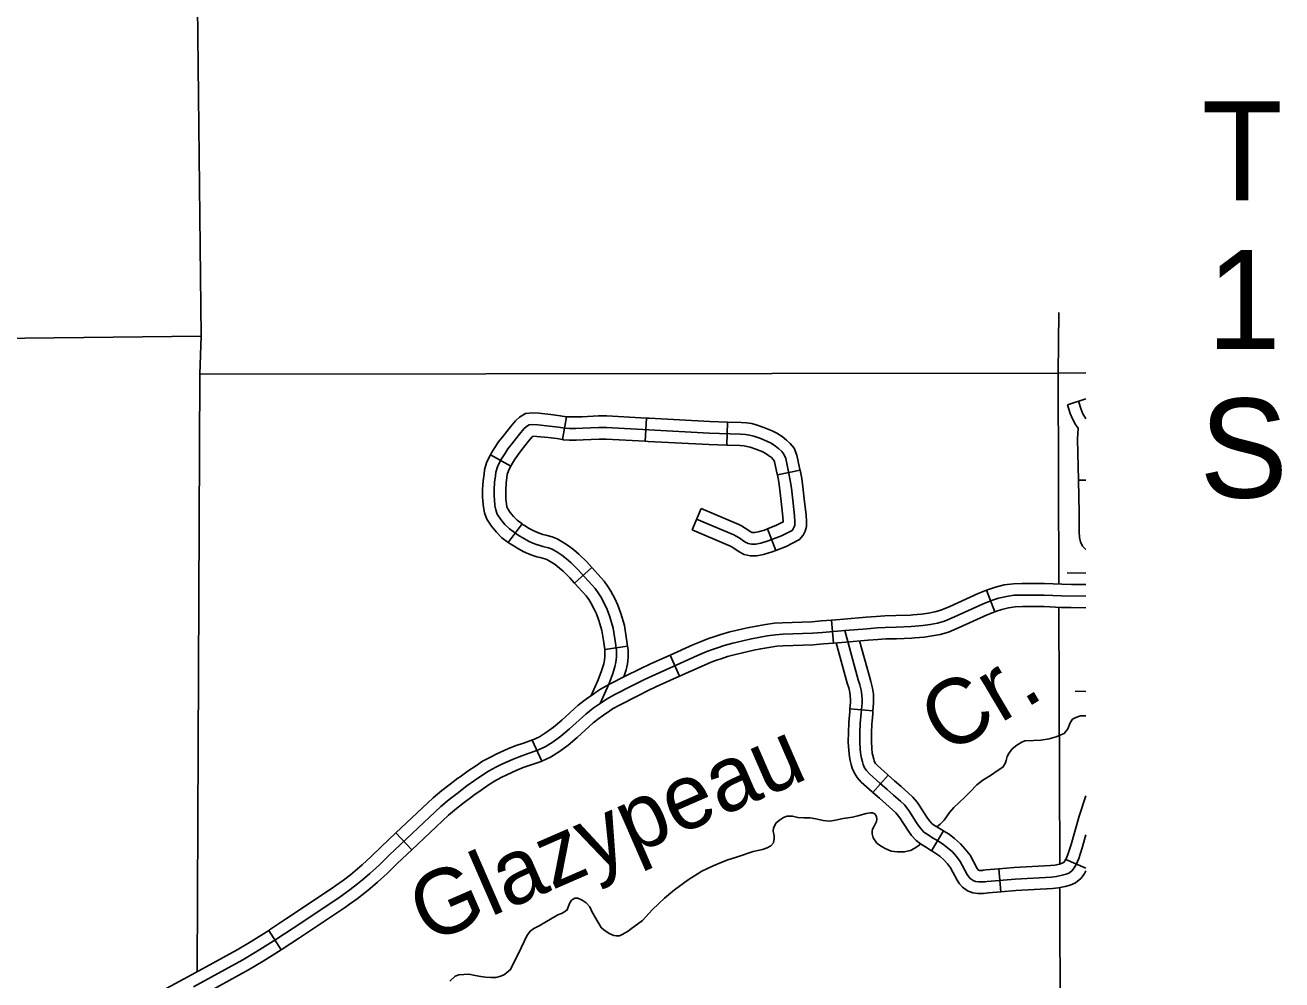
# Model space of a CAD drawing. Extents: x -3711 to 825, y -151 to 1050.
# Drawn here: x -2612.2 to -2520.9, y 335.8 to 405.1 of the extents above; entities that cross this region are included whole.
import ezdxf

# ---------------------------------------------------------------- set-up
doc = ezdxf.new("R2010")
doc.units = 0
for name, color, linetype in [('Default', 7, 'Continuous'), ('Level 31', 7, 'Continuous'), ('Level 32', 7, 'Continuous'), ('Level 35', 7, 'Continuous'), ('Level 4', 7, 'Continuous'), ('Level 5', 7, 'Continuous')]:
    doc.layers.add(name, color=color, linetype=linetype)

msp = doc.modelspace()

# ---------------------------------------------------------------- linework, layer by layer
at = {"layer": 'Level 31'}
for p, q in [((-2541.757, 362.511), (-2542.373, 364.075)), ((-2553.612, 361.903), (-2553.471, 360.228)), ((-2564.648, 357.829), (-2565.343, 359.359)), ((-2574.658, 351.659), (-2575.35, 353.191)), ((-2574.658, 351.659), (-2574.658, 351.659)), ((-2585.247, 346.438), (-2584.093, 345.215)), ((-2593.591, 337.939), (-2594.49, 339.36))]:
    msp.add_line(p, q, dxfattribs=at)
for points in [[(-2535.146, 365.319), (-2536.513, 365.34)], [(-2542.373, 364.075), (-2542.295, 364.106), (-2541.716, 364.299), (-2541.077, 364.453), (-2540.412, 364.544), (-2539.769, 364.564), (-2538.999, 364.564), (-2538.145, 364.564), (-2536.896, 364.505), (-2536.19, 364.494)], [(-2536.19, 364.494), (-2535.146, 364.478)], [(-2535.146, 363.638), (-2536.923, 363.665), (-2538.165, 363.723), (-2538.999, 363.723), (-2539.756, 363.723), (-2540.342, 363.706), (-2540.921, 363.626), (-2541.483, 363.49), (-2542.007, 363.315), (-2542.648, 363.063), (-2544.686, 362.131), (-2545.406, 361.83), (-2545.923, 361.679), (-2546.451, 361.582), (-2546.995, 361.509), (-2547.83, 361.431), (-2548.917, 361.393), (-2549.712, 361.373), (-2550.314, 361.334), (-2551.032, 361.276), (-2552.654, 361.14), (-2554.273, 361.004), (-2554.991, 360.946), (-2557.16, 360.87), (-2557.677, 360.838), (-2558.291, 360.752), (-2558.916, 360.644), (-2559.436, 360.538), (-2560.791, 360.223), (-2561.415, 360.052), (-2561.901, 359.897)], [(-2542.373, 364.075), (-2542.977, 363.837), (-2545.023, 362.901), (-2545.687, 362.623), (-2546.117, 362.498), (-2546.582, 362.412), (-2547.09, 362.344), (-2547.715, 362.286)], [(-2541.756, 362.511), (-2542.319, 362.289), (-2544.349, 361.36), (-2545.125, 361.036), (-2545.729, 360.86), (-2546.319, 360.751), (-2546.901, 360.674), (-2547.56, 360.612)], [(-2536.216, 362.813), (-2536.949, 362.825), (-2538.184, 362.883), (-2538.999, 362.883), (-2539.743, 362.883), (-2540.272, 362.867), (-2540.764, 362.799), (-2541.251, 362.681), (-2541.72, 362.525), (-2541.756, 362.511)], [(-2535.146, 362.797), (-2536.216, 362.813)], [(-2559.594, 361.364), (-2559.071, 361.47), (-2558.421, 361.582), (-2557.762, 361.675), (-2557.201, 361.71), (-2555.04, 361.785), (-2554.342, 361.842), (-2553.612, 361.903)], [(-2547.715, 362.286), (-2547.884, 362.271), (-2548.942, 362.233), (-2549.75, 362.213), (-2550.375, 362.173), (-2551.101, 362.114), (-2552.725, 361.978), (-2553.612, 361.903)], [(-2565.343, 359.359), (-2563.687, 360.111), (-2562.973, 360.402), (-2562.553, 360.561), (-2562.166, 360.695), (-2561.654, 360.858), (-2560.997, 361.038), (-2559.614, 361.359), (-2559.593, 361.364)], [(-2547.56, 360.612), (-2547.776, 360.592), (-2548.891, 360.552), (-2549.675, 360.533), (-2550.253, 360.496), (-2550.963, 360.438), (-2552.584, 360.303), (-2553.471, 360.228)], [(-2561.901, 359.897), (-2562.267, 359.77), (-2562.665, 359.619), (-2563.355, 359.339), (-2566.403, 357.955), (-2567.199, 357.584), (-2568.169, 357.098), (-2569.353, 356.496), (-2569.955, 356.166), (-2570.411, 355.855), (-2570.925, 355.506), (-2571.469, 355.078), (-2572.653, 354.01), (-2573.274, 353.466), (-2573.836, 353.058), (-2574.419, 352.689), (-2575.02, 352.417), (-2575.641, 352.204), (-2576.301, 351.971), (-2576.79, 351.781), (-2577.563, 351.427), (-2577.986, 351.209), (-2578.524, 350.929), (-2578.941, 350.65), (-2579.537, 350.25), (-2580.097, 349.851), (-2580.804, 349.31), (-2581.386, 348.863), (-2581.988, 348.358), (-2585.733, 344.823), (-2586.471, 344.105), (-2587.15, 343.502), (-2587.671, 343.037), (-2588.038, 342.745), (-2588.566, 342.336), (-2589.402, 341.735), (-2592.724, 339.522), (-2593.974, 338.691), (-2595.321, 337.84), (-2596.366, 337.225), (-2599.959, 335.248)], [(-2559.257, 359.716), (-2560.585, 359.408), (-2561.176, 359.246), (-2561.635, 359.099), (-2561.98, 358.98), (-2562.358, 358.837), (-2563.023, 358.567), (-2564.648, 357.829)], [(-2553.471, 360.228), (-2554.204, 360.166), (-2554.943, 360.106), (-2557.119, 360.03), (-2557.592, 360.001), (-2558.161, 359.921), (-2558.761, 359.817), (-2559.259, 359.716)], [(-2565.343, 359.359), (-2566.755, 358.718), (-2567.565, 358.341), (-2568.548, 357.849), (-2569.746, 357.239), (-2570.395, 356.883), (-2570.754, 356.639)], [(-2564.648, 357.829), (-2566.052, 357.191), (-2566.833, 356.827), (-2567.791, 356.348), (-2568.96, 355.753), (-2569.515, 355.448), (-2569.808, 355.249)], [(-2570.754, 356.639), (-2570.884, 356.55), (-2571.422, 356.184), (-2572.011, 355.721), (-2573.211, 354.638), (-2573.798, 354.124), (-2574.309, 353.754), (-2574.819, 353.431), (-2575.351, 353.191)], [(-2535.146, 356.722), (-2535.934, 356.734)], [(-2569.808, 355.249), (-2569.938, 355.16), (-2570.428, 354.827), (-2570.927, 354.435), (-2572.094, 353.382), (-2572.749, 352.808), (-2573.364, 352.362), (-2574.019, 351.948), (-2574.658, 351.659)], [(-2575.331, 353.2), (-2575.918, 352.997), (-2576.594, 352.759), (-2577.117, 352.555), (-2577.93, 352.183), (-2578.372, 351.956), (-2578.954, 351.653), (-2579.409, 351.348), (-2580.015, 350.941), (-2580.597, 350.527), (-2580.751, 350.409)], [(-2579.729, 349.074), (-2579.598, 349.175), (-2579.059, 349.558), (-2578.472, 349.952), (-2578.095, 350.205), (-2577.6, 350.463), (-2577.195, 350.67), (-2576.462, 351.006), (-2576.009, 351.182), (-2575.365, 351.41), (-2574.71, 351.635), (-2574.658, 351.659)], [(-2580.751, 350.409), (-2581.315, 349.977), (-2581.912, 349.519), (-2582.547, 348.986), (-2585.247, 346.438)], [(-2584.093, 345.215), (-2581.429, 347.73), (-2580.86, 348.207), (-2580.292, 348.643), (-2579.729, 349.074)], [(-2585.247, 346.438), (-2586.315, 345.43), (-2587.043, 344.72), (-2587.709, 344.13), (-2588.214, 343.68), (-2588.557, 343.407), (-2589.069, 343.009), (-2589.611, 342.62)], [(-2584.093, 345.215), (-2585.152, 344.216), (-2585.899, 343.489), (-2586.591, 342.875), (-2587.129, 342.394), (-2587.519, 342.084), (-2588.063, 341.662), (-2588.63, 341.255)], [(-2589.611, 342.62), (-2589.88, 342.426), (-2593.19, 340.222), (-2594.431, 339.397), (-2594.49, 339.36)], [(-2588.63, 341.255), (-2588.923, 341.044), (-2592.259, 338.822), (-2593.517, 337.986), (-2593.591, 337.939)], [(-2594.49, 339.36), (-2595.759, 338.557), (-2596.782, 337.956), (-2599.567, 336.424)], [(-2598.756, 334.951), (-2595.95, 336.494), (-2594.883, 337.122), (-2593.591, 337.939)], [(-2599.567, 336.424), (-2600.361, 335.986), (-2602.198, 335), (-2604.774, 333.647)]]:
    msp.add_lwpolyline(points, dxfattribs=at)
at = {"layer": 'Level 32'}
for p, q in [((-2536.487, 377.532), (-2535.146, 377.978)), ((-2572.871, 376.671), (-2573.159, 375.015)), ((-2567.057, 376.574), (-2567.152, 374.896)), ((-2561.165, 376.288), (-2561.222, 374.607)), ((-2578.378, 373.92), (-2576.918, 373.087)), ((-2555.904, 372.794), (-2557.551, 372.458)), ((-2535.681, 372.058), (-2535.146, 372.07)), ((-2563.748, 368.469), (-2563.088, 370.015)), ((-2577.094, 367.545), (-2576.093, 368.895)), ((-2557.657, 366.966), (-2558.263, 368.534)), ((-2572.275, 364.591), (-2571.025, 365.715)), ((-2570.092, 359.778), (-2568.426, 360.003)), ((-2552.281, 355.46), (-2550.606, 355.318)), ((-2550.615, 349.382), (-2549.496, 350.636)), ((-2546.348, 345.147), (-2545.49, 346.593)), ((-2535.146, 343.876), (-2536.605, 344.515)), ((-2541.314, 342.16), (-2541.459, 343.835))]:
    msp.add_line(p, q, dxfattribs=at)
for points in [[(-2572.871, 376.671), (-2573.314, 376.748), (-2573.995, 376.829), (-2574.871, 376.928), (-2575.337, 376.952), (-2575.839, 376.913), (-2576.272, 376.653), (-2576.576, 376.379), (-2576.927, 375.939), (-2577.467, 375.264), (-2577.805, 374.841), (-2578.062, 374.435), (-2578.303, 374.052), (-2578.378, 373.92)], [(-2536.487, 377.532), (-2536.283, 376.919), (-2536.12, 376.513), (-2535.89, 376.114), (-2535.72, 375.876), (-2535.712, 375.864), (-2535.712, 375.851), (-2535.745, 375.04), (-2535.681, 372.058)], [(-2535.689, 377.797), (-2535.493, 377.208), (-2535.362, 376.881), (-2535.182, 376.57), (-2535.146, 376.519)], [(-2563.418, 369.242), (-2560.714, 368.088), (-2560.546, 368.004), (-2560.336, 367.881), (-2559.904, 367.588), (-2559.675, 367.474), (-2559.434, 367.423), (-2559.116, 367.423), (-2558.76, 367.486), (-2558.213, 367.652), (-2557.259, 368.021), (-2556.484, 368.415), (-2556.395, 368.53), (-2556.319, 368.67), (-2556.28, 368.81), (-2556.28, 369.051), (-2556.306, 369.484), (-2556.408, 370.387), (-2556.535, 371.481), (-2556.611, 372.054), (-2556.738, 372.677), (-2556.942, 373.644), (-2557.069, 373.95), (-2557.234, 374.153), (-2557.437, 374.344), (-2557.695, 374.549), (-2558.01, 374.759), (-2558.261, 374.885), (-2558.823, 375.108), (-2559.268, 375.26), (-2559.586, 375.349), (-2559.875, 375.389), (-2560.224, 375.414), (-2562.5, 375.492), (-2566.897, 375.723), (-2569.964, 375.897), (-2570.523, 375.897), (-2571.68, 375.839), (-2572.182, 375.82), (-2572.645, 375.82), (-2572.992, 375.839), (-2573.436, 375.916), (-2574.091, 375.994), (-2574.94, 376.09), (-2575.326, 376.109), (-2575.576, 376.09), (-2575.769, 375.974), (-2575.962, 375.801), (-2576.271, 375.414), (-2576.811, 374.739), (-2577.119, 374.353), (-2577.351, 373.986), (-2577.582, 373.62), (-2577.736, 373.349), (-2577.871, 373.04), (-2577.987, 372.654), (-2578.021, 372.382), (-2578.091, 371.93), (-2578.122, 371.361), (-2578.122, 370.898), (-2578.103, 370.628), (-2578.064, 370.223), (-2578.006, 369.914), (-2577.891, 369.605), (-2577.64, 369.219), (-2577.331, 368.852), (-2577.004, 368.524), (-2576.483, 368.138), (-2576.31, 368.032), (-2576.039, 367.868), (-2575.634, 367.636), (-2575.306, 367.482), (-2575.039, 367.384), (-2574.796, 367.314), (-2574.576, 367.257), (-2574.168, 367.154), (-2573.917, 367.048), (-2573.493, 366.806), (-2573.204, 366.613), (-2572.857, 366.343), (-2572.529, 366.073), (-2572.008, 365.552), (-2570.784, 364.191), (-2570.553, 363.878), (-2570.369, 363.583), (-2570.099, 363.081), (-2569.906, 362.676), (-2569.713, 362.135), (-2569.482, 361.325), (-2569.327, 360.398), (-2569.231, 359.684), (-2569.231, 359.221), (-2569.27, 358.854), (-2569.347, 358.507), (-2569.52, 357.947), (-2569.792, 357.241), (-2570.411, 355.855)], [(-2567.057, 376.574), (-2569.94, 376.738), (-2570.544, 376.738), (-2571.718, 376.679), (-2572.198, 376.66), (-2572.621, 376.66), (-2572.896, 376.676), (-2572.871, 376.671)], [(-2561.165, 376.288), (-2562.464, 376.332), (-2566.851, 376.563), (-2567.057, 376.574)], [(-2555.904, 372.794), (-2555.915, 372.848), (-2556.135, 373.895), (-2556.339, 374.385), (-2556.617, 374.727), (-2556.887, 374.981), (-2557.199, 375.229), (-2557.587, 375.488), (-2557.918, 375.653), (-2558.532, 375.896), (-2559.018, 376.063), (-2559.415, 376.175), (-2559.788, 376.225), (-2560.179, 376.254), (-2561.165, 376.288)], [(-2573.159, 375.015), (-2573.557, 375.084), (-2574.188, 375.158), (-2575.008, 375.252), (-2575.299, 375.266), (-2575.348, 375.222), (-2575.614, 374.89), (-2576.154, 374.214), (-2576.433, 373.865), (-2576.64, 373.538), (-2576.861, 373.187), (-2576.918, 373.087)], [(-2567.152, 374.896), (-2569.988, 375.056), (-2570.502, 375.056), (-2571.643, 374.999), (-2572.166, 374.979), (-2572.668, 374.979), (-2573.088, 375.003), (-2573.159, 375.015)], [(-2561.222, 374.607), (-2562.536, 374.652), (-2566.943, 374.884), (-2567.152, 374.896)], [(-2557.551, 372.458), (-2557.561, 372.507), (-2557.748, 373.394), (-2557.798, 373.514), (-2557.851, 373.579), (-2557.988, 373.708), (-2558.191, 373.87), (-2558.433, 374.031), (-2558.605, 374.117), (-2559.114, 374.319), (-2559.518, 374.457), (-2559.757, 374.524), (-2559.963, 374.552), (-2560.269, 374.575), (-2561.222, 374.607)], [(-2578.378, 373.92), (-2578.489, 373.727), (-2578.662, 373.331), (-2578.813, 372.828), (-2578.854, 372.498), (-2578.928, 372.018), (-2578.963, 371.385), (-2578.963, 370.868), (-2578.941, 370.558), (-2578.898, 370.105), (-2578.819, 369.687), (-2578.646, 369.224), (-2578.317, 368.717), (-2577.951, 368.283), (-2577.554, 367.886), (-2577.094, 367.545)], [(-2576.918, 373.087), (-2576.984, 372.971), (-2577.081, 372.75), (-2577.162, 372.48), (-2577.189, 372.266), (-2577.254, 371.843), (-2577.282, 371.338), (-2577.282, 370.928), (-2577.265, 370.698), (-2577.231, 370.34), (-2577.194, 370.14), (-2577.136, 369.986), (-2576.963, 369.72), (-2576.711, 369.421), (-2576.453, 369.162), (-2576.093, 368.895)], [(-2558.263, 368.534), (-2557.603, 368.789), (-2557.121, 369.034), (-2557.144, 369.412), (-2557.243, 370.292), (-2557.369, 371.377), (-2557.44, 371.914), (-2557.551, 372.458)], [(-2557.657, 366.966), (-2556.916, 367.252), (-2555.935, 367.751), (-2555.689, 368.068), (-2555.533, 368.354), (-2555.44, 368.697), (-2555.44, 369.076), (-2555.468, 369.556), (-2555.572, 370.483), (-2555.701, 371.585), (-2555.782, 372.194), (-2555.904, 372.794)], [(-2535.681, 372.058), (-2535.631, 369.698), (-2535.635, 368.309), (-2535.613, 367.893), (-2535.529, 367.591), (-2535.38, 367.271), (-2535.146, 367.037)], [(-2563.088, 370.015), (-2560.36, 368.851), (-2560.144, 368.743), (-2559.887, 368.592), (-2559.478, 368.315), (-2559.396, 368.274), (-2559.346, 368.263), (-2559.19, 368.263), (-2558.956, 368.305), (-2558.487, 368.447), (-2558.263, 368.534)], [(-2576.093, 368.895), (-2576.011, 368.835), (-2575.872, 368.749), (-2575.613, 368.592), (-2575.246, 368.382), (-2574.982, 368.258), (-2574.778, 368.184), (-2574.573, 368.125), (-2574.366, 368.071), (-2573.901, 367.953), (-2573.545, 367.804), (-2573.051, 367.522), (-2572.712, 367.295), (-2572.331, 366.999), (-2571.963, 366.696), (-2571.398, 366.13), (-2571.025, 365.715)], [(-2563.748, 368.469), (-2561.067, 367.325), (-2560.948, 367.265), (-2560.786, 367.17), (-2560.329, 366.861), (-2559.954, 366.673), (-2559.521, 366.582), (-2559.041, 366.582), (-2558.563, 366.667), (-2557.939, 366.856), (-2557.657, 366.966)], [(-2577.094, 367.545), (-2576.955, 367.441), (-2576.748, 367.314), (-2576.465, 367.143), (-2576.023, 366.89), (-2575.631, 366.705), (-2575.299, 366.584), (-2575.019, 366.504), (-2574.786, 366.442), (-2574.435, 366.354), (-2574.29, 366.293), (-2573.936, 366.091), (-2573.696, 365.931), (-2573.382, 365.687), (-2573.095, 365.45), (-2572.619, 364.973), (-2572.275, 364.591)], [(-2571.025, 365.715), (-2570.133, 364.723), (-2569.858, 364.352), (-2569.641, 364.005), (-2569.349, 363.461), (-2569.129, 362.999), (-2568.912, 362.392), (-2568.66, 361.51), (-2568.496, 360.524), (-2568.426, 360.003)], [(-2572.275, 364.591), (-2571.436, 363.658), (-2571.249, 363.405), (-2571.096, 363.161), (-2570.849, 362.701), (-2570.683, 362.353), (-2570.514, 361.878), (-2570.303, 361.14), (-2570.159, 360.273), (-2570.092, 359.778)], [(-2552.654, 361.14), (-2551.676, 357.561), (-2551.561, 357.202), (-2551.461, 356.801), (-2551.418, 356.457), (-2551.404, 356.17), (-2551.4, 355.897), (-2551.461, 355.174), (-2551.485, 354.89), (-2551.508, 354.667), (-2551.531, 354.398), (-2551.554, 353.744), (-2551.561, 353.058), (-2551.531, 352.498), (-2551.485, 352.098), (-2551.438, 351.883), (-2551.369, 351.606), (-2551.323, 351.414), (-2551.216, 351.176), (-2551.089, 350.965), (-2550.87, 350.73), (-2550.114, 350.062), (-2549.584, 349.588), (-2549.111, 349.187), (-2548.61, 348.742), (-2548.323, 348.47), (-2548.08, 348.169), (-2547.958, 347.992), (-2547.392, 347.108), (-2547.148, 346.778), (-2546.905, 346.508), (-2546.682, 346.339), (-2546.289, 346.09), (-2545.902, 345.86), (-2545.558, 345.645), (-2545.222, 345.393), (-2544.841, 345.057), (-2544.546, 344.732), (-2544.268, 344.369), (-2543.762, 343.425)], [(-2570.092, 359.778), (-2570.072, 359.628), (-2570.072, 359.265), (-2570.101, 358.99), (-2570.16, 358.723), (-2570.315, 358.223), (-2570.568, 357.564), (-2571.081, 356.416)], [(-2568.426, 360.003), (-2568.39, 359.741), (-2568.39, 359.177), (-2568.439, 358.719), (-2568.534, 358.291), (-2568.694, 357.775)], [(-2553.281, 360.244), (-2552.482, 357.322), (-2552.37, 356.972), (-2552.289, 356.646), (-2552.256, 356.384), (-2552.244, 356.143), (-2552.241, 355.927), (-2552.281, 355.46)], [(-2551.577, 360.387), (-2550.87, 357.8), (-2550.752, 357.433), (-2550.633, 356.955), (-2550.58, 356.53), (-2550.564, 356.197), (-2550.559, 355.867), (-2550.606, 355.318)], [(-2552.281, 355.46), (-2552.299, 355.244), (-2552.322, 354.967), (-2552.344, 354.746), (-2552.37, 354.448), (-2552.394, 353.764), (-2552.402, 353.04), (-2552.369, 352.427), (-2552.315, 351.962), (-2552.257, 351.693), (-2552.186, 351.406), (-2552.122, 351.141), (-2551.961, 350.785), (-2551.764, 350.456), (-2551.457, 350.127), (-2550.673, 349.433), (-2550.615, 349.382)], [(-2550.606, 355.318), (-2550.624, 355.105), (-2550.647, 354.813), (-2550.671, 354.588), (-2550.691, 354.347), (-2550.713, 353.724), (-2550.721, 353.077), (-2550.693, 352.57), (-2550.654, 352.235), (-2550.619, 352.073), (-2550.553, 351.806), (-2550.524, 351.687), (-2550.47, 351.567), (-2550.414, 351.473), (-2550.282, 351.332), (-2549.556, 350.69), (-2549.496, 350.636)], [(-2549.496, 350.636), (-2549.032, 350.222), (-2548.56, 349.822), (-2548.041, 349.362), (-2547.704, 349.041), (-2547.406, 348.673), (-2547.258, 348.458), (-2546.699, 347.584), (-2546.497, 347.31), (-2546.334, 347.13), (-2546.202, 347.03), (-2545.849, 346.806), (-2545.49, 346.593)], [(-2550.615, 349.382), (-2550.136, 348.954), (-2549.662, 348.552), (-2549.178, 348.123), (-2548.942, 347.898), (-2548.753, 347.665), (-2548.658, 347.527), (-2548.085, 346.631), (-2547.8, 346.245), (-2547.476, 345.886), (-2547.162, 345.648), (-2546.728, 345.373), (-2546.348, 345.147)], [(-2536.605, 344.515), (-2536.445, 344.88), (-2536.218, 345.6), (-2535.63, 347.655), (-2535.146, 349.136)], [(-2545.49, 346.594), (-2545.464, 346.578), (-2545.082, 346.339), (-2544.691, 346.046), (-2544.25, 345.657), (-2543.9, 345.271), (-2543.559, 344.826), (-2543.036, 343.848), (-2542.979, 343.759), (-2542.974, 343.753), (-2542.936, 343.726), (-2542.88, 343.718), (-2542.673, 343.718), (-2542.596, 343.728), (-2542.411, 343.753), (-2541.459, 343.835)], [(-2543.762, 343.425), (-2543.652, 343.25), (-2543.54, 343.125), (-2543.337, 342.978), (-2543.151, 342.906), (-2542.936, 342.878), (-2542.621, 342.878), (-2542.487, 342.894), (-2542.318, 342.917), (-2540.285, 343.093), (-2537.634, 343.236), (-2537.276, 343.279), (-2536.863, 343.363), (-2536.578, 343.448), (-2536.33, 343.552), (-2536.13, 343.709), (-2535.987, 343.91), (-2535.848, 344.148), (-2535.657, 344.584), (-2535.413, 345.358), (-2535.146, 346.293)], [(-2546.348, 345.147), (-2546.339, 345.142), (-2546.034, 344.951), (-2545.754, 344.741), (-2545.433, 344.458), (-2545.192, 344.193), (-2544.977, 343.912), (-2544.489, 343.001), (-2544.325, 342.742), (-2544.106, 342.497), (-2543.741, 342.233), (-2543.36, 342.086), (-2542.992, 342.037), (-2542.569, 342.037), (-2542.378, 342.061), (-2542.225, 342.082), (-2541.314, 342.16)], [(-2541.459, 343.835), (-2540.344, 343.931), (-2537.707, 344.074), (-2537.41, 344.11), (-2537.067, 344.18), (-2536.861, 344.241), (-2536.76, 344.283), (-2536.744, 344.296), (-2536.693, 344.367), (-2536.599, 344.529), (-2536.605, 344.515)], [(-2541.314, 342.16), (-2540.226, 342.254), (-2537.561, 342.398), (-2537.142, 342.449), (-2536.659, 342.547), (-2536.295, 342.655), (-2535.901, 342.82), (-2535.516, 343.123), (-2535.28, 343.453), (-2535.146, 343.684)]]:
    msp.add_lwpolyline(points, dxfattribs=at)
at = {"layer": 'Level 35'}
for points in [[(-2545.976, 346.89), (-2545.718, 347.066), (-2545.427, 347.377), (-2545.039, 347.921), (-2544.747, 348.29), (-2544.398, 348.601), (-2543.893, 349.087), (-2543.543, 349.437), (-2543.058, 349.942), (-2542.631, 350.272), (-2542.068, 350.622), (-2541.505, 350.991), (-2541.175, 351.224), (-2541.019, 351.477), (-2540.942, 351.71), (-2540.864, 351.982), (-2540.747, 352.215), (-2540.495, 352.546), (-2540.165, 352.818), (-2539.796, 353.031), (-2539.582, 353.129), (-2538.961, 353.167), (-2538.417, 353.187), (-2537.816, 353.284), (-2537.311, 353.42), (-2536.961, 353.556), (-2536.728, 353.673), (-2536.456, 354.003), (-2536.282, 354.43), (-2536.107, 354.702), (-2535.874, 354.838), (-2535.544, 354.936), (-2535.146, 354.952)], [(-2581.347, 335.68), (-2580.94, 336.029), (-2580.687, 336.127), (-2580.318, 336.165), (-2579.969, 336.185), (-2579.503, 336.088), (-2579.076, 336.01), (-2578.746, 335.971), (-2578.357, 335.932), (-2577.988, 335.932), (-2577.639, 336.029), (-2577.367, 336.165), (-2576.921, 336.515), (-2576.726, 336.923), (-2576.338, 337.681), (-2575.736, 338.963), (-2575.503, 339.294), (-2575.231, 339.507), (-2574.843, 339.682), (-2574.435, 339.935), (-2573.503, 340.479), (-2573.231, 340.596), (-2572.998, 340.712), (-2572.824, 340.848), (-2572.727, 341.12), (-2572.629, 341.373), (-2572.513, 341.548), (-2572.261, 341.703), (-2572.047, 341.703), (-2571.717, 341.567), (-2571.445, 341.373), (-2571.173, 341.081), (-2570.998, 340.693), (-2570.591, 339.974), (-2570.358, 339.566), (-2570.164, 339.391), (-2569.756, 339.138), (-2569.426, 338.983), (-2569.251, 338.963), (-2569.173, 338.963), (-2569.018, 338.963), (-2568.824, 339.061), (-2568.377, 339.313), (-2568.241, 339.43), (-2567.348, 340.09), (-2566.63, 340.868), (-2565.756, 341.703), (-2565.018, 342.306), (-2564.028, 343.044), (-2563.038, 343.666), (-2562.222, 344.054), (-2561.232, 344.462), (-2560.455, 344.715), (-2559.31, 345.084), (-2558.63, 345.24), (-2558.3, 345.356), (-2558.028, 345.512), (-2557.834, 345.725), (-2557.795, 346.036), (-2557.795, 346.231), (-2557.853, 346.561), (-2557.834, 346.794), (-2557.659, 347.144), (-2557.407, 347.377), (-2557.116, 347.571), (-2556.844, 347.668), (-2556.455, 347.649), (-2556.067, 347.552), (-2555.64, 347.532), (-2555.174, 347.532), (-2554.747, 347.455), (-2554.223, 347.338), (-2553.737, 347.299), (-2553.329, 347.358), (-2552.766, 347.494), (-2552.106, 347.591), (-2551.698, 347.688), (-2551.097, 347.843), (-2550.805, 347.902), (-2550.631, 347.902), (-2550.475, 347.824), (-2550.359, 347.63), (-2550.339, 347.416), (-2550.359, 347.26), (-2550.456, 347.086), (-2550.553, 346.891), (-2550.631, 346.716), (-2550.669, 346.561), (-2550.669, 346.367), (-2550.592, 346.095), (-2550.32, 345.706), (-2550.067, 345.492), (-2549.718, 345.298)], [(-2549.718, 345.298), (-2549.291, 345.123), (-2548.844, 345.065), (-2548.339, 345.065), (-2547.893, 345.162), (-2547.563, 345.337), (-2547.252, 345.55), (-2547.188, 345.642)]]:
    msp.add_lwpolyline(points, dxfattribs=at)
at = {"layer": 'Level 4'}
msp.add_lwpolyline([(-2599.692, 408.7), (-2599.405, 382.523), (-2599.496, 379.775), (-2599.69, 336.389)], dxfattribs=at)
at = {"layer": 'Level 5'}
for points in [[(-2537.109, 364.534), (-2537.155, 379.851), (-2537.11, 384.238)], [(-2654.878, 381.905), (-2599.405, 382.523)], [(-2535.146, 379.86), (-2537.155, 379.851), (-2599.496, 379.775)], [(-2537.049, 344.238), (-2537.104, 362.775)], [(-2536.984, 322.452), (-2537.044, 342.413)]]:
    msp.add_lwpolyline(points, dxfattribs=at)

# ---------------------------------------------------------------- texts
at = {"layer": 'Default'}
for s, p in [('T', (-2526.74, 392.398)), ('1', (-2526.35, 381.598)), ('S', (-2526.893, 370.798))]:
    msp.add_text(s, height=7.2, dxfattribs=at).set_placement(p)
at = {"layer": 'Level 35'}
for s, rotation, p in [('Cr.', 30.62636, (-2545.309, 352.048)), ('Glazypeau', 23.56643, (-2582.923, 338.347))]:
    msp.add_text(s, height=4.7343, rotation=rotation, dxfattribs=at).set_placement(p)

doc.saveas('drawing.dxf')
